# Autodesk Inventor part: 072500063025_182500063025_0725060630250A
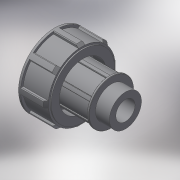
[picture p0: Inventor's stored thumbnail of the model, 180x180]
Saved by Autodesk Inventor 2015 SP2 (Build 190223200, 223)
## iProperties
Created: 2017-04
Part Number: 072500063025_182500063025_0725060630250A
Material: Generic
Description: PLASSON THREADED ADAPTOR 63-2.1/2"
Document SubType Name: Modeling
Designer: KIM
Density: 1 g/cm^3
Appearance: Default
Author: KIM
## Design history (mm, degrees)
derived "07250.ipt"
feature "Solid1::07250.ipt"
tag "TaggingFeature1"
body "Solid1"
other parameters: "d1" = 75.184, "d2" = 116, "d3" = 29, "d6" = 113, "d7" = 105.09, "d8" = 90.4, "d9" = 63, "d10" = 82.7024, "d12" = 45.1104, "d13" = 52.6288, "d14" = 33.35, "d15" = 84.75, "d16" = 3.48, "d17" = 46.4, "d18" = 29, "d19" = 34.8, "d24" = 15.0368, "d25" = 7.5184, "d27" = 0, "d28" = 6.01472, "d31" = 1.50368, "d35" = 360 deg, "d41" = 29.337, "d56" = 69.3, "d57" = 6.3, "d58" = 3.15, "d60" = 0, "d61" = 0.75184, "d64" = 0.75184, "d68" = 360 deg, "d_" = 63, "R_" = 75.184, "E_" = 113, "H_" = 116, "l_2" = 29, "d55" = 63
